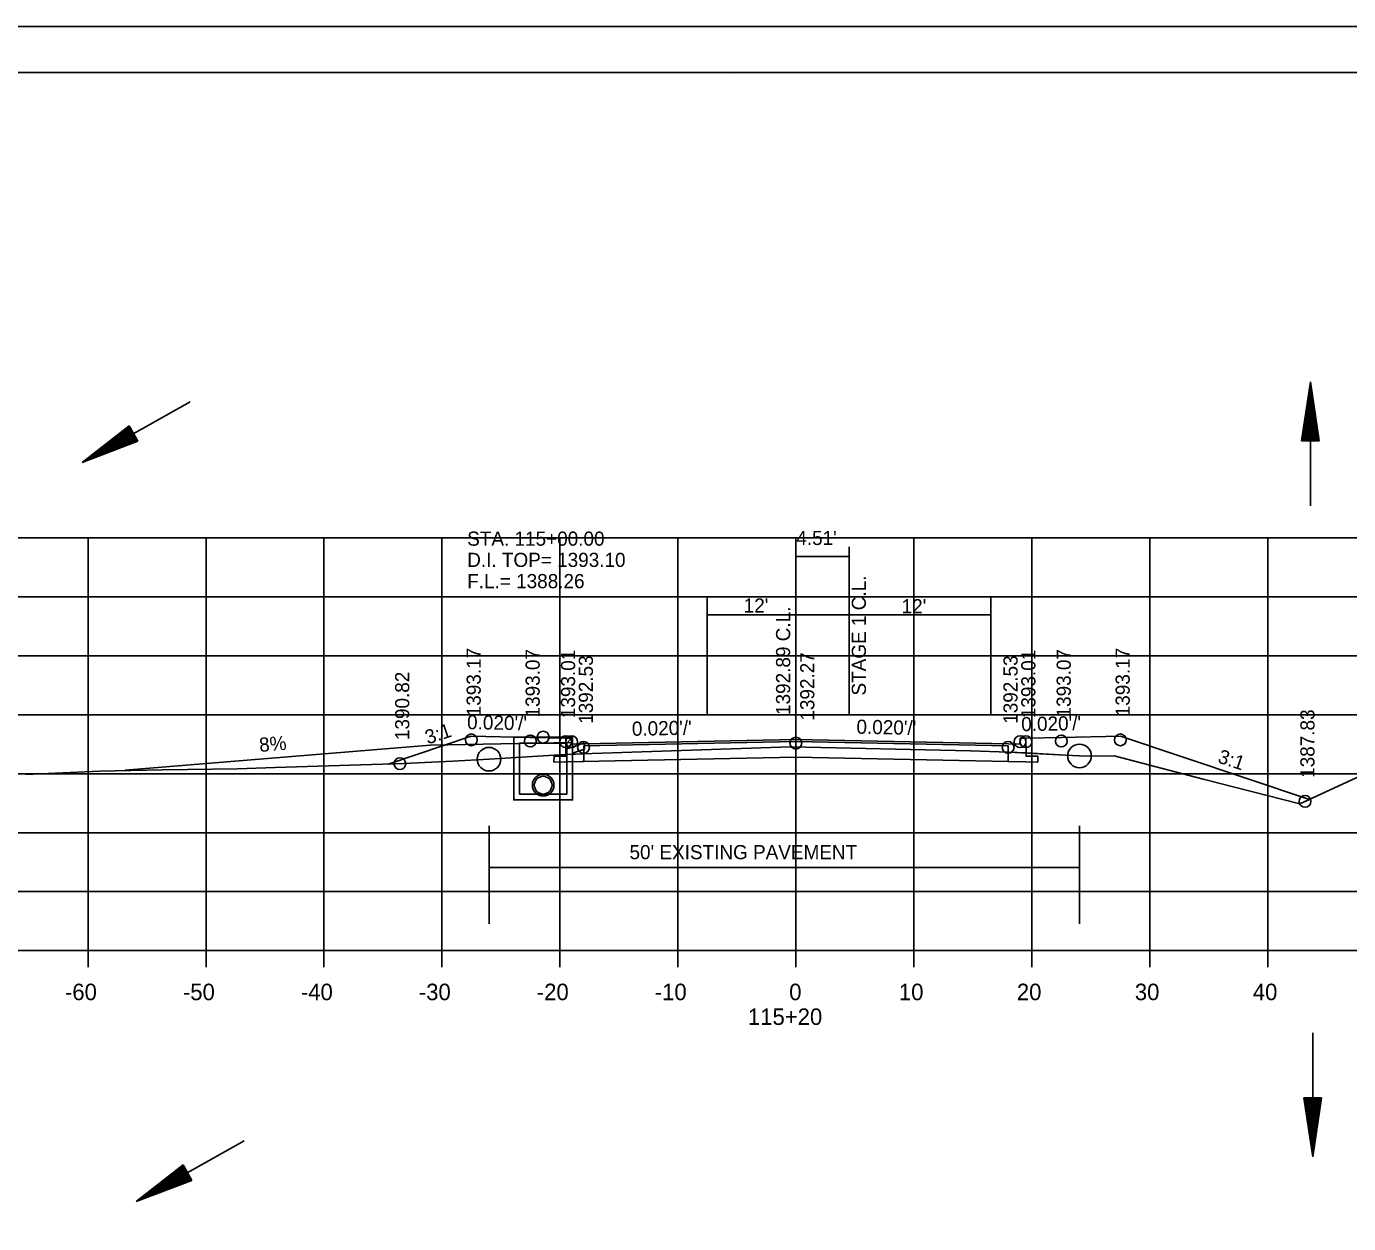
# Model space of a CAD drawing. Extents: x 1374311 to 1383814, y 384102 to 406278.
# Drawn here: x 1382655.6 to 1382767.7, y 387791.1 to 387892.6 of the extents above; entities that cross this region are included whole.
import ezdxf

# ---------------------------------------------------------------- set-up
doc = ezdxf.new("R2010")
doc.units = 0
for name, color, linetype in [('R_Axis', 7, 'Continuous'), ('R_Axis Annot', 7, 'Continuous'), ('R_Border', 7, 'Continuous'), ('R_Draft', 7, 'Continuous'), ('R_Exist Surface', 7, 'Continuous'), ('R_Fin Surface', 7, 'Continuous'), ('R_Grid', 7, 'Continuous'), ('R_No Plot', 7, 'Continuous'), ('R_Water', 7, 'Continuous'), ('R_Water Annot', 7, 'Continuous'), ('R_Xsect Elev', 7, 'Continuous'), ('R_Xsect Slope', 7, 'Continuous')]:
    doc.layers.add(name, color=color, linetype=linetype)

msp = doc.modelspace()

# ---------------------------------------------------------------- linework, layer by layer
at = {"layer": 'R_Axis'}
for p, q in [((1382580.86, 387814.27), (1382860.86, 387814.27)), ((1382660.86, 387812.87), (1382660.86, 387814.27)), ((1382670.86, 387812.87), (1382670.86, 387814.27)), ((1382680.86, 387812.87), (1382680.86, 387814.27)), ((1382690.86, 387812.87), (1382690.86, 387814.27)), ((1382700.86, 387812.87), (1382700.86, 387814.27)), ((1382710.86, 387812.87), (1382710.86, 387814.27)), ((1382720.86, 387812.87), (1382720.86, 387814.27)), ((1382730.86, 387812.87), (1382730.86, 387814.27)), ((1382740.86, 387812.87), (1382740.86, 387814.27)), ((1382750.86, 387812.87), (1382750.86, 387814.27)), ((1382760.86, 387812.87), (1382760.86, 387814.27))]:
    msp.add_line(p, q, dxfattribs=at)
at = {"layer": 'R_Border'}
for p, q in [((1382562.86, 387888.73), (1382879.04, 387888.73)), ((1382715.38, 387888.47), (1382715.38, 387888.47)), ((1382715.38, 387888.47), (1382715.38, 387888.47))]:
    msp.add_line(p, q, dxfattribs=at)
at = {"layer": 'R_Draft'}
for p, q in [((1382763.73, 387857.48), (1382764.48, 387862.48)), ((1382765.23, 387857.48), (1382764.48, 387862.48)), ((1382763.85, 387857.48), (1382764.48, 387861.65)), ((1382765.1, 387857.48), (1382764.48, 387861.65)), ((1382763.98, 387857.48), (1382764.48, 387860.79)), ((1382764.1, 387857.48), (1382764.48, 387859.95)), ((1382764.97, 387857.48), (1382764.48, 387860.79)), ((1382764.85, 387857.48), (1382764.48, 387859.95)), ((1382664.34, 387858.77), (1382660.35, 387855.66)), ((1382664.4, 387858.66), (1382661.08, 387856.07)), ((1382665.08, 387857.46), (1382664.34, 387858.77)), ((1382764.23, 387857.48), (1382764.48, 387859.11)), ((1382764.72, 387857.48), (1382764.48, 387859.11)), ((1382665.02, 387857.57), (1382661.08, 387856.07)), ((1382664.46, 387858.55), (1382661.83, 387856.49)), ((1382664.95, 387857.68), (1382661.83, 387856.49)), ((1382664.53, 387858.44), (1382662.55, 387856.9)), ((1382664.89, 387857.79), (1382662.55, 387856.9)), ((1382664.59, 387858.33), (1382663.29, 387857.32)), ((1382664.83, 387857.9), (1382663.29, 387857.32)), ((1382664.65, 387858.22), (1382664.02, 387857.73)), ((1382664.77, 387858.01), (1382664.02, 387857.73)), ((1382764.36, 387857.48), (1382764.48, 387858.27)), ((1382764.59, 387857.48), (1382764.48, 387858.27)), ((1382665.08, 387857.46), (1382660.35, 387855.66)), ((1382763.73, 387857.48), (1382765.23, 387857.48)), ((1382763.93, 387801.8), (1382764.68, 387796.8)), ((1382765.43, 387801.8), (1382763.93, 387801.8)), ((1382764.05, 387801.8), (1382764.68, 387797.63)), ((1382764.18, 387801.8), (1382764.68, 387798.49)), ((1382764.3, 387801.8), (1382764.68, 387799.33)), ((1382764.43, 387801.8), (1382764.68, 387800.17)), ((1382764.56, 387801.8), (1382764.68, 387801.01)), ((1382765.43, 387801.8), (1382764.68, 387796.8)), ((1382764.92, 387801.8), (1382764.68, 387800.17)), ((1382765.17, 387801.8), (1382764.68, 387798.49)), ((1382765.3, 387801.8), (1382764.68, 387797.63)), ((1382765.05, 387801.8), (1382764.68, 387799.33)), ((1382764.79, 387801.8), (1382764.68, 387801.01)), ((1382668.92, 387796.1), (1382664.93, 387793)), ((1382668.99, 387795.99), (1382665.66, 387793.4)), ((1382669.66, 387794.79), (1382668.92, 387796.1)), ((1382669.66, 387794.79), (1382664.93, 387793)), ((1382669.6, 387794.9), (1382665.66, 387793.4)), ((1382669.05, 387795.88), (1382666.41, 387793.83)), ((1382669.54, 387795.01), (1382666.41, 387793.83)), ((1382669.11, 387795.77), (1382667.14, 387794.23)), ((1382669.47, 387795.12), (1382667.14, 387794.23)), ((1382669.17, 387795.66), (1382667.87, 387794.65)), ((1382669.41, 387795.23), (1382667.87, 387794.65)), ((1382669.23, 387795.55), (1382668.6, 387795.06)), ((1382669.35, 387795.34), (1382668.6, 387795.06))]:
    msp.add_line(p, q, dxfattribs=at)
at = {"layer": 'R_Exist Surface'}
msp.add_lwpolyline([(1382655.59, 387829.21), (1382661.84, 387829.48), (1382667.18, 387829.61), (1382673.52, 387829.69), (1382676.72, 387829.79), (1382687.64, 387830.13), (1382691.77, 387830.34), (1382694.85, 387830.5), (1382699.93, 387830.82), (1382700.79, 387830.87), (1382703.6, 387830.97), (1382720.44, 387831.55), (1382735.68, 387831.2), (1382738.93, 387831.11), (1382743.73, 387830.85), (1382744.91, 387830.78), (1382745.78, 387830.75), (1382747.85, 387830.79), (1382755.4, 387828.82), (1382763.59, 387826.71), (1382769.04, 387829.24)], dxfattribs=at)
msp.add_circle((1382699.44, 387828.3), 0.917, dxfattribs=at)
at = {"layer": 'R_Fin Surface'}
for points in [[(1382686.29, 387830.09), (1382693.35, 387832.44), (1382698.35, 387832.34), (1382701.35, 387832.28), (1382701.85, 387832.28), (1382701.86, 387831.78), (1382702.86, 387831.8), (1382720.86, 387832.16), (1382738.86, 387831.8), (1382739.86, 387831.78), (1382739.87, 387832.28), (1382740.37, 387832.28), (1382743.37, 387832.34), (1382748.37, 387832.44), (1382764.41, 387827.09)], [(1382740.37, 387832.28), (1382740.38, 387830.75), (1382741.38, 387830.75), (1382741.37, 387830.25), (1382740.37, 387830.27), (1382738.86, 387830.3), (1382738.86, 387831.63), (1382720.86, 387831.99), (1382702.9, 387831.63), (1382702.9, 387830.3), (1382701.35, 387830.27), (1382700.35, 387830.25), (1382700.36, 387830.75), (1382701.36, 387830.75), (1382701.35, 387832.28)]]:
    msp.add_lwpolyline(points, dxfattribs=at)
at = {"layer": 'R_Grid'}
for p, q in [((1382580.86, 387849.27), (1382860.86, 387849.27)), ((1382660.86, 387814.27), (1382660.86, 387849.27)), ((1382670.86, 387814.27), (1382670.86, 387849.27)), ((1382680.86, 387814.27), (1382680.86, 387849.27)), ((1382690.86, 387814.27), (1382690.86, 387849.27)), ((1382700.86, 387814.27), (1382700.86, 387849.27)), ((1382710.86, 387814.27), (1382710.86, 387849.27)), ((1382720.86, 387814.27), (1382720.86, 387849.27)), ((1382730.86, 387814.27), (1382730.86, 387849.27)), ((1382740.86, 387814.27), (1382740.86, 387849.27)), ((1382750.86, 387814.27), (1382750.86, 387849.27)), ((1382760.86, 387814.27), (1382760.86, 387849.27)), ((1382580.86, 387844.27), (1382860.86, 387844.27)), ((1382580.86, 387839.27), (1382860.86, 387839.27)), ((1382580.86, 387834.27), (1382860.86, 387834.27)), ((1382580.86, 387829.27), (1382860.86, 387829.27)), ((1382580.86, 387824.27), (1382860.86, 387824.27)), ((1382580.86, 387819.27), (1382860.86, 387819.27)), ((1382580.86, 387814.27), (1382860.86, 387814.27))]:
    msp.add_line(p, q, dxfattribs=at)
at = {"layer": 'R_No Plot'}
msp.add_line((1382550.46, 387892.62), (1382883.79, 387892.62), dxfattribs=at)
for points in [[(1382550.45, 387892.62), (1382883.79, 387892.62), (1382883.79, 387679.29), (1382550.45, 387679.29)], [(1382796.78, 387888.73), (1382796.78, 387878.85), (1382832.51, 387878.85), (1382832.51, 387875.93), (1382855.71, 387875.93), (1382855.71, 387852.71), (1382879.04, 387852.71), (1382879.04, 387683.27), (1382562.86, 387683.27), (1382562.86, 387888.73)], [(1382686.29, 387830.09), (1382687.64, 387830.13), (1382691.77, 387830.34), (1382694.85, 387830.5), (1382699.93, 387830.82), (1382700.79, 387830.87), (1382701.36, 387830.89), (1382701.35, 387832.28), (1382698.35, 387832.34), (1382693.35, 387832.44)], [(1382740.38, 387831.03), (1382743.73, 387830.85), (1382744.91, 387830.78), (1382745.78, 387830.75), (1382747.85, 387830.79), (1382755.4, 387828.82), (1382763.59, 387826.71), (1382764.41, 387827.09), (1382748.37, 387832.44), (1382743.37, 387832.34), (1382740.37, 387832.28)], [(1382701.36, 387830.89), (1382703.6, 387830.97), (1382720.44, 387831.55), (1382735.68, 387831.2), (1382738.93, 387831.11), (1382740.38, 387831.03), (1382740.38, 387830.75), (1382741.38, 387830.75), (1382741.37, 387830.25), (1382740.37, 387830.27), (1382738.86, 387830.3), (1382738.86, 387830.3), (1382720.86, 387830.66), (1382701.35, 387830.27), (1382700.35, 387830.25), (1382700.36, 387830.75), (1382701.36, 387830.75)]]:
    msp.add_lwpolyline(points, close=True, dxfattribs=at)
for centre, radius in [((1382693.35, 387832.14), 0.5), ((1382698.35, 387832.04), 0.5), ((1382699.44, 387832.37), 0.5), ((1382701.35, 387831.98), 0.5), ((1382701.85, 387831.98), 0.5), ((1382702.86, 387831.5), 0.5), ((1382720.86, 387831.86), 0.5), ((1382738.86, 387831.5), 0.5), ((1382739.87, 387831.98), 0.5), ((1382740.37, 387831.98), 0.5), ((1382743.37, 387832.04), 0.5), ((1382744.91, 387830.78), 1), ((1382748.37, 387832.14), 0.5), ((1382694.85, 387830.5), 1), ((1382687.29, 387830.12), 0.5), ((1382687.29, 387830.12), 0.5), ((1382764.03, 387826.92), 0.5)]:
    msp.add_circle(centre, radius, dxfattribs=at)
at = {"layer": 'R_Water'}
for p, q in [((1382764.48, 387851.98), (1382764.48, 387862.48)), ((1382669.51, 387860.81), (1382660.35, 387855.66)), ((1382720.86, 387846.3), (1382720.86, 387848.51)), ((1382720.86, 387847.68), (1382725.37, 387847.68)), ((1382725.37, 387834.27), (1382725.37, 387848.51)), ((1382720.86, 387844.27), (1382720.86, 387846.3)), ((1382713.33, 387834.27), (1382713.33, 387844.22)), ((1382737.4, 387834.27), (1382737.4, 387844.22)), ((1382713.33, 387842.75), (1382737.4, 387842.75)), ((1382720.86, 387834.27), (1382720.86, 387842.49)), ((1382696.94, 387832.37), (1382701.69, 387832.37)), ((1382696.94, 387830.87), (1382696.94, 387832.37)), ((1382697.44, 387830.87), (1382697.44, 387831.87)), ((1382697.44, 387831.87), (1382701.44, 387831.87)), ((1382701.77, 387832.2), (1382701.44, 387831.87)), ((1382702.94, 387831.89), (1382701.44, 387831.37)), ((1382701.77, 387832.2), (1382701.69, 387832.37)), ((1382701.44, 387830.87), (1382701.44, 387831.37)), ((1382702.94, 387831.36), (1382701.94, 387831.01)), ((1382701.94, 387830.87), (1382701.94, 387831.01)), ((1382694.85, 387816.54), (1382694.85, 387824.86)), ((1382744.91, 387816.54), (1382744.91, 387824.86)), ((1382694.85, 387821.33), (1382744.91, 387821.33)), ((1382764.68, 387807.31), (1382764.68, 387796.8)), ((1382674.09, 387798.14), (1382664.93, 387793))]:
    msp.add_line(p, q, dxfattribs=at)
for points in [[(1382664.01, 387829.58), (1382689.86, 387831.68), (1382701.85, 387831.92)], [(1382702.94, 387831.36), (1382702.94, 387831.89)]]:
    msp.add_lwpolyline(points, dxfattribs=at)
for points in [[(1382699.44, 387832.37), (1382701.94, 387832.37), (1382701.94, 387827.05), (1382699.44, 387827.05), (1382696.94, 387827.05), (1382696.94, 387832.37)], [(1382699.44, 387831.87), (1382701.44, 387831.87), (1382701.44, 387827.55), (1382699.44, 387827.55), (1382697.44, 387827.55), (1382697.44, 387831.87)]]:
    msp.add_lwpolyline(points, close=True, dxfattribs=at)
msp.add_circle((1382699.44, 387828.3), 0.75, dxfattribs=at)

# ---------------------------------------------------------------- texts
at = {"layer": 'R_Axis Annot'}
for s, p in [('-60', (1382658.9, 387810.07)), ('-50', (1382668.9, 387810.07)), ('-40', (1382678.9, 387810.07)), ('-30', (1382688.9, 387810.07)), ('-20', (1382698.9, 387810.07)), ('-10', (1382708.9, 387810.07)), ('0', (1382720.3, 387810.07)), ('10', (1382729.6, 387810.07)), ('20', (1382739.6, 387810.07)), ('30', (1382749.6, 387810.07)), ('40', (1382759.6, 387810.07)), ('115+20', (1382716.8, 387807.97))]:
    msp.add_text(s, height=1.4, dxfattribs=at).set_placement(p)
at = {"layer": 'R_Water'}
for s, p in [("4.51'", (1382720.9, 387848.66)), ("12'", (1382716.44, 387842.93)), ("12'", (1382729.83, 387842.87)), ("50' EXISTING PAVEMENT", (1382706.76, 387822.02))]:
    msp.add_text(s, height=1.2, dxfattribs=at).set_placement(p)
for s, rotation, p in [('STAGE 1 C.L.', 90, (1382726.8, 387835.9)), ('8%', 4.6618, (1382675.41, 387831.11))]:
    msp.add_text(s, height=1.2, rotation=rotation, dxfattribs=at).set_placement(p)
at = {"layer": 'R_Water Annot'}
for s, p in [('STA. 115+00.00', (1382693, 387848.6)), ('D.I. TOP= 1393.10', (1382693, 387846.8)), ('F.L.= 1388.26', (1382693, 387845))]:
    msp.add_text(s, height=1.2, dxfattribs=at).set_placement(p)
at = {"layer": 'R_Xsect Elev'}
for s, p in [('1392.89 C.L.', (1382720.38, 387834.25)), ('1393.17', (1382694.15, 387834.14)), ('1393.07', (1382699.15, 387834.04)), ('1393.01', (1382702.15, 387833.98)), ('1393.01', (1382741.17, 387833.98)), ('1393.07', (1382744.17, 387834.04)), ('1393.17', (1382749.17, 387834.14)), ('1392.53', (1382703.66, 387833.5)), ('1392.27', (1382722.43, 387833.77)), ('1392.53', (1382739.66, 387833.5)), ('1390.82', (1382688.09, 387832.12)), ('1387.83', (1382764.83, 387828.92))]:
    msp.add_text(s, height=1.2, rotation=90, dxfattribs=at).set_placement(p)
at = {"layer": 'R_Xsect Slope'}
for s, rotation, p in [("0.020'/'", 358.8542, (1382692.98, 387833.05)), ("0.020'/'", 1.1458, (1382739.98, 387832.87)), ('3:1', 18.4349, (1382689.66, 387831.74)), ("0.020'/'", 1.1458, (1382706.97, 387832.48)), ("0.020'/'", 358.8542, (1382725.99, 387832.66)), ('3:1', 341.5651, (1382756.55, 387830.24))]:
    msp.add_text(s, height=1.2, rotation=rotation, dxfattribs=at).set_placement(p)

doc.saveas('drawing.dxf')
